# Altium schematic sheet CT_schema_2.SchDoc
size 276 x 169 mm
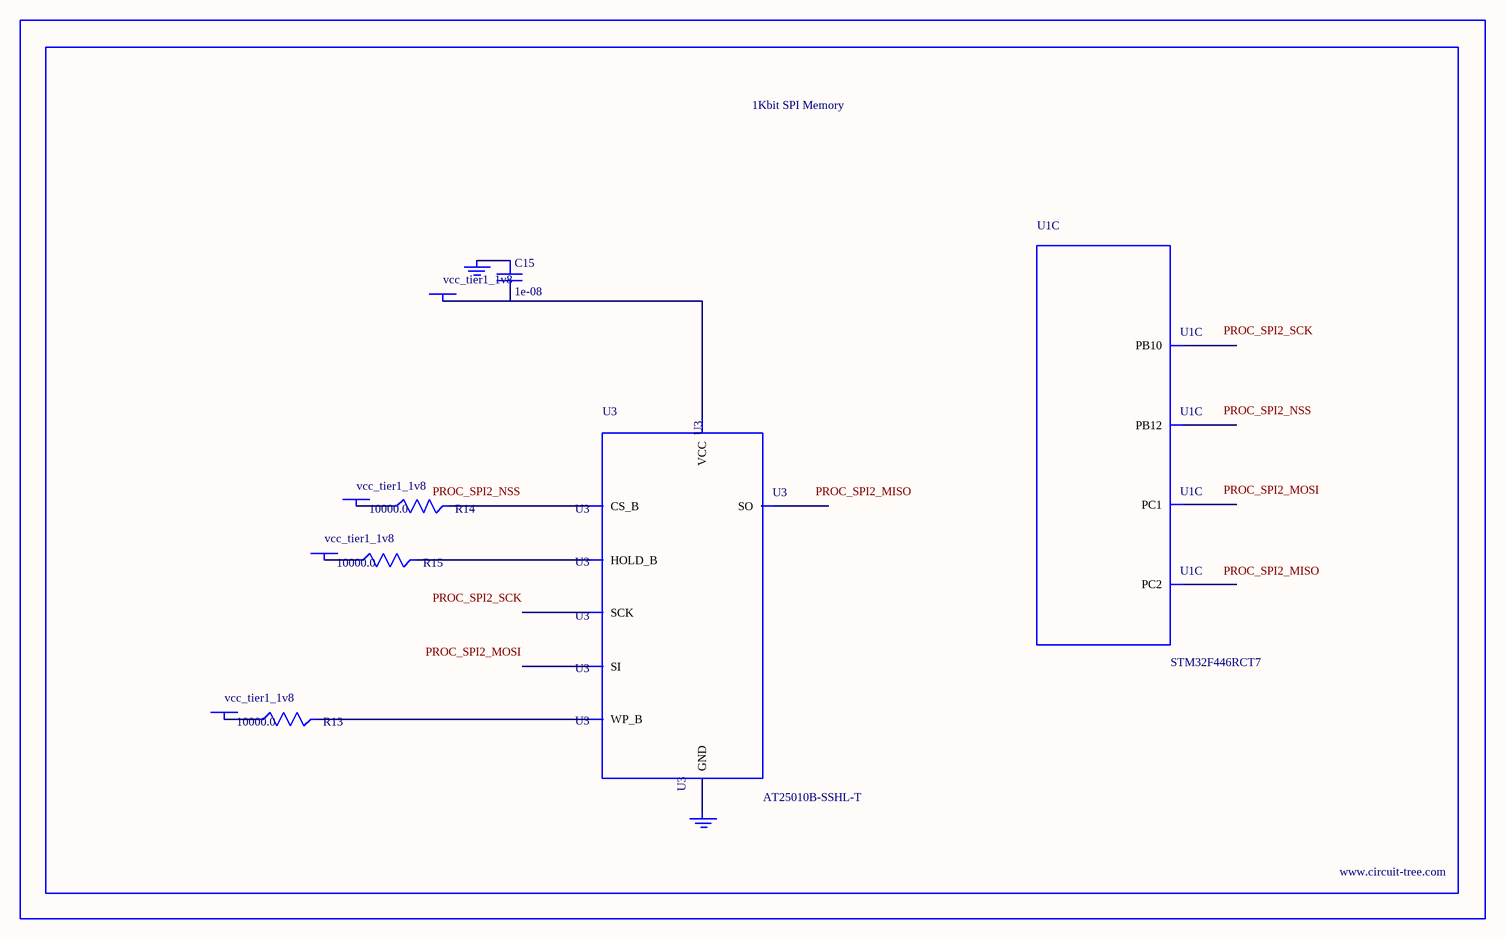
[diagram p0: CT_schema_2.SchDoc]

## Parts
BORDER1  (no value)
C15  1e-08  [C0402]
GND_INSTANCE_1_0  (no value)
GND_INSTANCE_1_1  (no value)
POWER_INSTANCE_1_0  vcc_tier1_1v8
POWER_INSTANCE_1_1  vcc_tier1_1v8
POWER_INSTANCE_1_2  vcc_tier1_1v8
POWER_INSTANCE_1_3  vcc_tier1_1v8
R13  10000.0  [R0603]
R14  10000.0  [R0603]
R15  10000.0  [R0603]
U1  STM32F446RCT7  [LQFP64]  (part C of 7)
U3  AT25010B-SSHL-T  [SOIC-8]

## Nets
NetC15_1: C15.1 GND_INSTANCE_1_0.0(GND)
NetC15_2: C15.2 POWER_INSTANCE_1_3.0(PWR) U3.8(VCC)
NetGND_INSTANCE_1_1_0: GND_INSTANCE_1_1.0(GND) U3.4(GND)
NetPOWER_INSTANCE_1_0_0: POWER_INSTANCE_1_0.0(PWR) R14.1
NetPOWER_INSTANCE_1_1_0: POWER_INSTANCE_1_1.0(PWR) R13.1
NetPOWER_INSTANCE_1_2_0: POWER_INSTANCE_1_2.0(PWR) R15.1
NetR13_2: R13.2 U3.3(WP_B)
NetR14_2: R14.2 U3.1(CS_B)
NetR15_2: R15.2 U3.7(HOLD_B)

Not connected (* = marked no-connect by the designer): U1 9(PC1) 10(PC2) 29(PB10) 33(PB12); U3 2(SO) 5(SI) 6(SCK)

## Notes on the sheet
- Labels drawn without touching a wire or pin: PROC_SPI2_MISO, PROC_SPI2_MOSI, PROC_SPI2_NSS, PROC_SPI2_SCK

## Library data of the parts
BORDER1 = BORDER_PAGE1
C15 = C0402C103K3RAC
GND_INSTANCE_1_0 GND_INSTANCE_1_1 = GND
POWER_INSTANCE_1_0-POWER_INSTANCE_1_3 = PWR
R13-R15 = RC0603JR-0710KL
